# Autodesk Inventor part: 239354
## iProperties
Company: Mayer & Müller AG Schaltgeräte
Created: 2006-01
Part Number: 239354
Material: Cu
Description: Senkniet
Document SubType Name: Modeling
Designer: I.Baliuc
Manufacturer: Standard
Standards Organization: Custom
Density: 8.94 g/cm^3
HalbzeugNorm: DIN 661
Zweck: Spule
Abmessung: 3 x 10
Author: T.Messerschmitt
Revision Number: 239354
Comments: DIN 661 - 3x10 - Cu
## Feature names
1. Drehung1 [Revolution]
